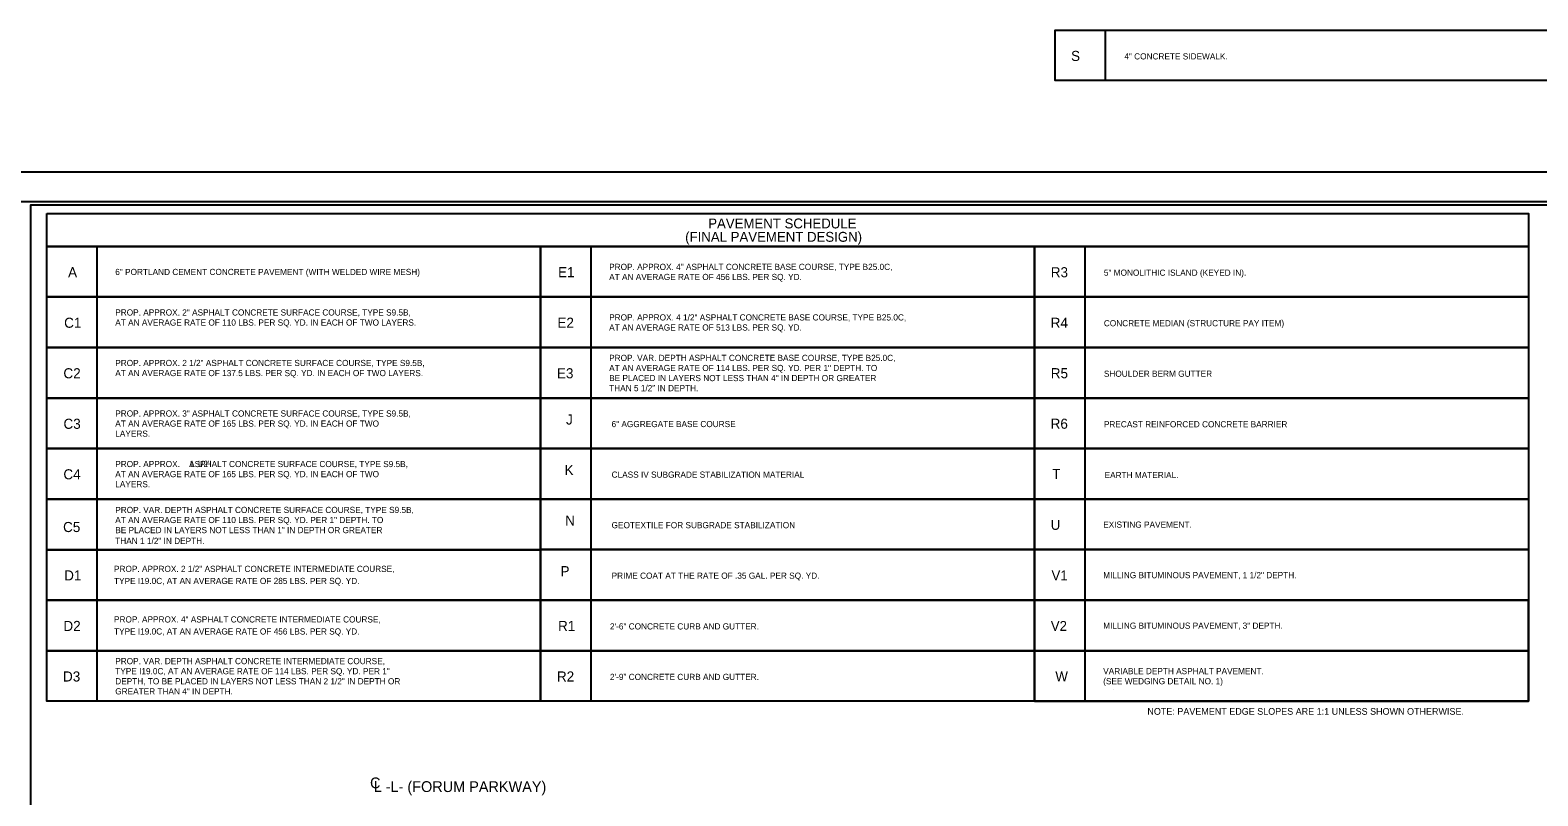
# Model space of a CAD drawing. Extents: x 1904401 to 1905163, y 193929 to 194736.
# Drawn here: x 1904744 to 1904973, y 194619.5 to 194735.8 of the extents above; entities that cross this region are included whole.
import ezdxf

# ---------------------------------------------------------------- set-up
doc = ezdxf.new("R2010")
doc.units = 0
for name, color, linetype in [('Prop Lane Arrow CELL', 7, 'Continuous'), ('Prop Pavement Schedule Description CELL', 7, 'Continuous'), ('Sheet Cutting Line CELL', 7, 'Continuous'), ('Sheet Plot Border Inside CELL', 7, 'Continuous'), ('Sheet Plot Border Outside CELL', 7, 'Continuous'), ('Sheet Typical CELL', 7, 'Continuous'), ('Typical Text Centerline CELL', 7, 'Continuous')]:
    doc.layers.add(name, color=color, linetype=linetype)

msp = doc.modelspace()

# ---------------------------------------------------------------- linework, layer by layer
at = {"layer": 'Prop Pavement Schedule Description CELL'}
msp.add_line((1904908.59, 194635.71), (1904908.59, 194635.71), dxfattribs=at)
for points in [[(1904907.33, 194728.11), (1904899.66, 194728.11), (1904899.66, 194735.78), (1904974.66, 194735.78), (1904974.66, 194728.11), (1904907.33, 194728.11), (1904907.33, 194735.78)], [(1904754.22, 194695.27), (1904746.55, 194695.27), (1904746.55, 194702.94), (1904821.55, 194702.94), (1904821.55, 194695.27), (1904754.22, 194695.27), (1904754.22, 194702.94)], [(1904829.22, 194695.27), (1904821.55, 194695.27), (1904821.55, 194702.94), (1904896.55, 194702.94), (1904896.55, 194695.27), (1904829.22, 194695.27), (1904829.22, 194702.94)], [(1904904.22, 194695.27), (1904896.55, 194695.27), (1904896.55, 194702.94), (1904971.55, 194702.94), (1904971.55, 194695.27), (1904904.22, 194695.27), (1904904.22, 194702.94)], [(1904754.22, 194687.59), (1904746.55, 194687.59), (1904746.55, 194695.27), (1904821.55, 194695.27), (1904821.55, 194687.59), (1904754.22, 194687.59), (1904754.22, 194695.27)], [(1904829.22, 194687.6), (1904821.55, 194687.6), (1904821.55, 194695.27), (1904896.55, 194695.27), (1904896.55, 194687.6), (1904829.22, 194687.6), (1904829.22, 194695.27)], [(1904904.22, 194687.59), (1904896.55, 194687.59), (1904896.55, 194695.27), (1904971.55, 194695.27), (1904971.55, 194687.59), (1904904.22, 194687.59), (1904904.22, 194695.27)], [(1904754.22, 194679.92), (1904746.55, 194679.92), (1904746.55, 194687.59), (1904821.55, 194687.59), (1904821.55, 194679.92), (1904754.22, 194679.92), (1904754.22, 194687.59)], [(1904829.22, 194679.93), (1904821.55, 194679.93), (1904821.55, 194687.6), (1904896.55, 194687.6), (1904896.55, 194679.93), (1904829.22, 194679.93), (1904829.22, 194687.6)], [(1904904.22, 194679.93), (1904896.55, 194679.93), (1904896.55, 194687.6), (1904971.55, 194687.6), (1904971.55, 194679.93), (1904904.22, 194679.93), (1904904.22, 194687.6)], [(1904754.22, 194672.25), (1904746.55, 194672.25), (1904746.55, 194679.92), (1904821.55, 194679.92), (1904821.55, 194672.25), (1904754.22, 194672.25), (1904754.22, 194679.92)], [(1904829.22, 194672.25), (1904821.55, 194672.25), (1904821.55, 194679.93), (1904896.57, 194679.93), (1904896.57, 194672.25), (1904829.22, 194672.25), (1904829.22, 194679.93)], [(1904904.22, 194672.26), (1904896.55, 194672.26), (1904896.55, 194679.93), (1904971.55, 194679.93), (1904971.55, 194672.26), (1904904.22, 194672.26), (1904904.22, 194679.93)], [(1904754.22, 194664.58), (1904746.55, 194664.58), (1904746.55, 194672.25), (1904821.55, 194672.25), (1904821.55, 194664.58), (1904754.22, 194664.58), (1904754.22, 194672.25)], [(1904829.22, 194664.58), (1904821.55, 194664.58), (1904821.55, 194672.25), (1904896.57, 194672.25), (1904896.57, 194664.58), (1904829.22, 194664.58), (1904829.22, 194672.25)], [(1904904.24, 194664.58), (1904896.57, 194664.58), (1904896.57, 194672.25), (1904971.57, 194672.25), (1904971.57, 194664.58), (1904904.24, 194664.58), (1904904.24, 194672.25)], [(1904754.22, 194656.9), (1904746.55, 194656.9), (1904746.55, 194664.57), (1904821.55, 194664.57), (1904821.55, 194656.9), (1904754.22, 194656.9), (1904754.22, 194664.57)], [(1904829.22, 194656.91), (1904821.55, 194656.91), (1904821.55, 194664.58), (1904896.57, 194664.58), (1904896.57, 194656.91), (1904829.22, 194656.91), (1904829.22, 194664.58)], [(1904904.24, 194656.91), (1904896.57, 194656.91), (1904896.57, 194664.58), (1904971.57, 194664.58), (1904971.57, 194656.91), (1904904.24, 194656.91), (1904904.24, 194664.58)], [(1904754.22, 194649.23), (1904746.55, 194649.23), (1904746.55, 194656.9), (1904821.55, 194656.9), (1904821.55, 194649.23), (1904754.22, 194649.23), (1904754.22, 194656.9)], [(1904829.22, 194649.23), (1904821.55, 194649.23), (1904821.55, 194656.91), (1904896.57, 194656.91), (1904896.57, 194649.23), (1904829.22, 194649.23), (1904829.22, 194656.91)], [(1904904.24, 194649.23), (1904896.57, 194649.23), (1904896.57, 194656.9), (1904971.57, 194656.91), (1904971.57, 194649.24), (1904904.24, 194649.23), (1904904.24, 194656.9)], [(1904754.22, 194641.56), (1904746.55, 194641.56), (1904746.55, 194649.23), (1904821.55, 194649.23), (1904821.55, 194641.56), (1904754.22, 194641.56), (1904754.22, 194649.23)], [(1904829.22, 194641.56), (1904821.55, 194641.56), (1904821.55, 194649.23), (1904896.55, 194649.23), (1904896.55, 194641.56), (1904829.22, 194641.56), (1904829.22, 194649.23)], [(1904904.24, 194641.57), (1904896.57, 194641.57), (1904896.57, 194649.24), (1904971.57, 194649.24), (1904971.57, 194641.57), (1904904.24, 194641.57), (1904904.24, 194649.24)], [(1904754.22, 194633.89), (1904746.55, 194633.89), (1904746.55, 194641.56), (1904821.55, 194641.56), (1904821.55, 194633.89), (1904754.22, 194633.89), (1904754.22, 194641.56)], [(1904829.22, 194633.89), (1904821.55, 194633.89), (1904821.55, 194641.56), (1904896.55, 194641.56), (1904896.55, 194633.89), (1904829.22, 194633.89), (1904829.22, 194641.56)], [(1904904.24, 194633.9), (1904896.57, 194633.9), (1904896.57, 194641.57), (1904971.58, 194641.57), (1904971.58, 194633.9), (1904904.24, 194633.9), (1904904.24, 194641.57)]]:
    msp.add_lwpolyline(points, dxfattribs=at)
for points in [[(1904746.55, 194707.92), (1904971.55, 194707.92), (1904971.55, 194702.94), (1904746.55, 194702.94)], [(1904971.57, 194649.24), (1904896.57, 194649.24), (1904896.57, 194633.89), (1904971.58, 194633.9)]]:
    msp.add_lwpolyline(points, close=True, dxfattribs=at)
at = {"layer": 'Sheet Cutting Line CELL'}
msp.add_line((1905047.49, 194714.2), (1904710.69, 194714.2), dxfattribs=at)
at = {"layer": 'Sheet Plot Border Inside CELL'}
msp.add_lwpolyline([(1905046.59, 194709.71), (1904713.29, 194709.71), (1904713.29, 194498.69), (1905046.59, 194498.69)], close=True, dxfattribs=at)
at = {"layer": 'Sheet Plot Border Outside CELL'}
msp.add_lwpolyline([(1905047.49, 194714.2), (1904710.69, 194714.2), (1904710.69, 194494.2), (1905047.49, 194494.2)], close=True, dxfattribs=at)
at = {"layer": 'Sheet Typical CELL'}
msp.add_lwpolyline([(1905044.09, 194709.2), (1904744.09, 194709.2), (1904744.09, 194499.2), (1905044.09, 194499.2)], close=True, dxfattribs=at)

# ---------------------------------------------------------------- texts
at = {"layer": 'Prop Lane Arrow CELL'}
for s, p in [('PAVEMENT SCHEDULE', (1904847, 194705.68)), ('(FINAL PAVEMENT DESIGN)', (1904843.5, 194703.65))]:
    msp.add_text(s, height=1.5, dxfattribs=at).set_placement(p)
at = {"layer": 'Prop Pavement Schedule Description CELL'}
for s, height, p in [('S ', 1.531, (1904902.1, 194731.1)), ('4" CONCRETE SIDEWALK.', 0.9375, (1904910.19, 194731.33)), ('A', 1.53, (1904749.8, 194698.27)), ('6" PORTLAND CEMENT CONCRETE PAVEMENT (WITH WELDED WIRE MESH)', 0.9375, (1904756.96, 194698.6)), ('E1', 1.531, (1904824.2, 194698.27)), ('AT AN AVERAGE RATE OF 456 LBS. PER SQ. YD.', 0.9375, (1904831.96, 194697.84)), ('PROP. APPROX. 4" ASPHALT CONCRETE BASE COURSE, TYPE B25.0C,', 0.9375, (1904831.96, 194699.37)), ('R3', 1.531, (1904899.02, 194698.26)), ('5" MONOLITHIC ISLAND (KEYED IN).', 0.9375, (1904907.08, 194698.49)), ('C1', 1.531, (1904749.2, 194690.59)), ('AT AN AVERAGE RATE OF 110 LBS. PER SQ. YD. IN EACH OF TWO LAYERS.', 0.9375, (1904756.96, 194690.92)), ('PROP. APPROX. 2" ASPHALT CONCRETE SURFACE COURSE, TYPE S9.5B, ', 0.9375, (1904756.96, 194692.45)), ('E2', 1.531, (1904824.1, 194690.6)), ('PROP. APPROX. 4 1/2" ASPHALT CONCRETE BASE COURSE, TYPE B25.0C, ', 0.9375, (1904831.96, 194691.7)), ('R4', 1.531, (1904899.01, 194690.59)), ('CONCRETE MEDIAN (STRUCTURE PAY ITEM)', 0.9375, (1904907.08, 194690.82)), ('AT AN AVERAGE RATE OF 513 LBS. PER SQ. YD.', 0.9375, (1904831.96, 194690.17)), ('PROP. APPROX. 2 1/2" ASPHALT CONCRETE SURFACE COURSE, TYPE S9.5B, ', 0.9375, (1904756.96, 194684.78)), ('AT AN AVERAGE RATE OF 114 LBS. PER SQ. YD. PER 1" DEPTH. TO', 0.9375, (1904831.96, 194684.02)), ('PROP. VAR. DEPTH ASPHALT CONCRETE BASE COURSE, TYPE B25.0C,', 0.9375, (1904831.96, 194685.55)), ('C2', 1.531, (1904749.09, 194682.92)), ('AT AN AVERAGE RATE OF 137.5 LBS. PER SQ. YD. IN EACH OF TWO LAYERS.', 0.9375, (1904756.96, 194683.25)), ('E3', 1.531, (1904824.03, 194682.92)), ('BE PLACED IN LAYERS NOT LESS THAN 4" IN DEPTH OR GREATER', 0.9375, (1904831.96, 194682.49)), ('R5', 1.531, (1904899.02, 194682.93)), ('SHOULDER BERM GUTTER', 0.9375, (1904907.08, 194683.15)), ('THAN 5 1/2" IN DEPTH. ', 0.9375, (1904831.96, 194680.96)), ('PROP. APPROX. 3" ASPHALT CONCRETE SURFACE COURSE, TYPE S9.5B, ', 0.9375, (1904756.96, 194677.11)), ('C3', 1.531, (1904749.1, 194675.25)), ('AT AN AVERAGE RATE OF 165 LBS. PER SQ. YD. IN EACH OF TWO ', 0.9375, (1904756.96, 194675.58)), ('J', 1.53, (1904825.41, 194675.9)), ('6" AGGREGATE BASE COURSE', 0.9377, (1904832.33, 194675.51)), ('R6', 1.531, (1904899, 194675.26)), ('PRECAST REINFORCED CONCRETE BARRIER', 0.9375, (1904907.08, 194675.48)), ('LAYERS.', 0.938, (1904756.96, 194674.05)), ('C4', 1.531, (1904749.09, 194667.58)), ('AT AN AVERAGE RATE OF 165 LBS. PER SQ. YD. IN EACH OF TWO ', 0.9375, (1904756.96, 194667.91)), ('PROP. APPROX.    ASPHALT CONCRETE SURFACE COURSE, TYPE S9.5B, ', 0.9375, (1904756.96, 194669.44)), (' 1 1/2" ', 0.938, (1904767.91, 194669.47)), ('K', 1.53, (1904825.19, 194668.23)), ('CLASS IV SUBGRADE STABILIZATION MATERIAL', 0.9377, (1904832.33, 194667.83)), ('T ', 1.5, (1904899.26, 194667.65)), ('LAYERS.', 0.938, (1904756.96, 194666.38)), ('EARTH MATERIAL.', 0.9375, (1904907.19, 194667.77)), ('AT AN AVERAGE RATE OF 110 LBS. PER SQ. YD. PER 1" DEPTH. TO', 0.9375, (1904756.96, 194660.94)), ('PROP. VAR. DEPTH ASPHALT CONCRETE SURFACE COURSE, TYPE S9.5B,', 0.9375, (1904756.96, 194662.47)), ('N', 1.53, (1904825.28, 194660.56)), ('C5', 1.531, (1904749.04, 194659.58)), ('BE PLACED IN LAYERS NOT LESS THAN 1" IN DEPTH OR GREATER', 0.9375, (1904756.96, 194659.41)), ('GEOTEXTILE FOR SUBGRADE STABILIZATION', 0.9377, (1904832.33, 194660.16)), ('U ', 1.5, (1904899.01, 194659.92)), ('EXISTING PAVEMENT.', 0.9375, (1904906.98, 194660.24)), ('THAN 1 1/2" IN DEPTH.', 0.9375, (1904756.96, 194657.77)), ('D1', 1.531, (1904749.2, 194652.23)), ('PROP. APPROX. 2 1/2" ASPHALT CONCRETE INTERMEDIATE COURSE,', 0.9375, (1904756.77, 194653.52)), ('P ', 1.532, (1904824.57, 194652.88)), ('PRIME COAT AT THE RATE OF .35 GAL. PER SQ. YD.', 0.9377, (1904832.33, 194652.49)), ('TYPE I19.0C, AT AN AVERAGE RATE OF 285 LBS. PER SQ. YD.', 0.9375, (1904756.77, 194651.69)), ('D2', 1.531, (1904749.09, 194644.56)), ('PROP. APPROX. 4" ASPHALT CONCRETE INTERMEDIATE COURSE,', 0.9375, (1904756.77, 194645.85)), ('R1', 1.531, (1904824.2, 194644.56)), ('TYPE I19.0C, AT AN AVERAGE RATE OF 456 LBS. PER SQ. YD.', 0.9375, (1904756.77, 194644.02)), ('2\'-6" CONCRETE CURB AND GUTTER.', 0.9375, (1904832.08, 194644.79)), ('PROP. VAR. DEPTH ASPHALT CONCRETE INTERMEDIATE COURSE,', 0.9375, (1904756.96, 194639.52)), ('D3', 1.531, (1904749.03, 194636.89)), ('TYPE I19.0C, AT AN AVERAGE RATE OF 114 LBS. PER SQ. YD. PER 1" ', 0.9375, (1904756.96, 194637.99)), ('DEPTH, TO BE PLACED IN LAYERS NOT LESS THAN 2 1/2" IN DEPTH OR', 0.9375, (1904756.96, 194636.46)), ('R2', 1.531, (1904824.03, 194636.89)), ('2\'-9" CONCRETE CURB AND GUTTER.', 0.9375, (1904832.08, 194637.12)), ('W', 1.5, (1904899.72, 194636.91)), ('VARIABLE DEPTH ASPHALT PAVEMENT.', 0.9375, (1904906.98, 194638)), ('(SEE WEDGING DETAIL NO. 1)', 0.9375, (1904906.98, 194636.47)), ('GREATER THAN 4" IN DEPTH.', 0.9375, (1904756.96, 194634.93)), ('NOTE: PAVEMENT EDGE SLOPES ARE 1:1 UNLESS SHOWN OTHERWISE.', 1.0203, (1904913.69, 194631.84))]:
    msp.add_text(s, height=height, dxfattribs=at).set_placement(p)
for s, height, p in [('V1', 1.5, (1904899.13, 194652.25)), ('MILLING BITUMINOUS PAVEMENT, 1 1/2" DEPTH.', 0.9375, (1904906.98, 194652.57)), ('V2', 1.5, (1904899.02, 194644.58)), ('MILLING BITUMINOUS PAVEMENT, 3" DEPTH.', 0.9375, (1904906.98, 194644.9))]:
    msp.add_text(s, height=height, rotation=0.0036, dxfattribs=at).set_placement(p)
at = {"layer": 'Typical Text Centerline CELL'}
msp.add_text('C', height=1.64, dxfattribs=at).set_placement((1904795.65, 194620.68))
msp.add_text('L -L- (FORUM PARKWAY)', height=1.6411, rotation=359.9469, dxfattribs=at).set_placement((1904796.2, 194620.12))

doc.saveas('drawing.dxf')
